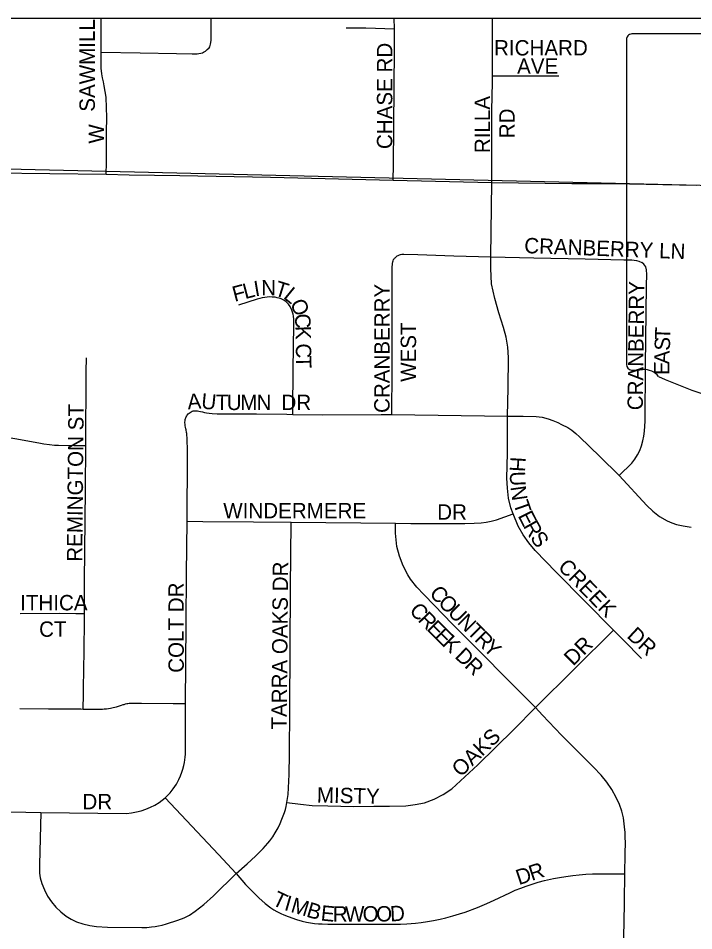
# Model space of a CAD drawing. Extents: x 0 to 68, y 0 to 52.9.
# Drawn here: x 57.097 to 58.195, y 51.458 to 52.941 of the extents above; entities that cross this region are included whole.
import ezdxf

# ---------------------------------------------------------------- set-up
doc = ezdxf.new("R2010")
doc.units = 0
for name, color, linetype in [('Default', 7, 'Continuous'), ('GM_X_State_Route', 7, 'Continuous'), ('GM_X_State_Shield', 7, 'Continuous')]:
    doc.layers.add(name, color=color, linetype=linetype)

msp = doc.modelspace()

# ---------------------------------------------------------------- linework, layer by layer
at = {"layer": 'Default'}
msp.add_line((49.5172, 52.9414), (67.9972, 52.9414), dxfattribs=at)
for points in [[(58.9659, 52.9414), (58.9639, 52.6515), (56.2737, 52.715), (56.2751, 52.9414)], [(57.2317, 52.8861), (57.2318, 52.9414)], [(57.4041, 52.8904), (57.4073, 52.8933), (57.4085, 52.8952), (57.4091, 52.8971), (57.4096, 52.8992), (57.41, 52.9021), (57.4104, 52.9058), (57.4107, 52.9093), (57.4104, 52.9414)], [(57.7083, 52.9241), (57.7082, 52.9414)], [(57.8676, 52.8476), (57.8676, 52.866), (57.8678, 52.9414)], [(57.6299, 52.9258), (57.6617, 52.9259), (57.7083, 52.9241)], [(57.7062, 52.6784), (57.7068, 52.7024), (57.7087, 52.8915), (57.7083, 52.9241)], [(57.2317, 52.8861), (57.2951, 52.885), (57.3543, 52.8839), (57.3799, 52.8834), (57.3844, 52.8834), (57.3878, 52.8836), (57.3908, 52.884), (57.3941, 52.8846), (57.3964, 52.8854), (57.3984, 52.8863), (57.4012, 52.888), (57.4041, 52.8904)], [(57.2403, 52.6877), (57.2404, 52.7066), (57.2407, 52.7561), (57.2409, 52.7806), (57.2405, 52.7959), (57.2398, 52.8129), (57.2387, 52.8222), (57.2368, 52.8318), (57.2355, 52.8381), (57.2342, 52.8445), (57.233, 52.8512), (57.2321, 52.8605), (57.2318, 52.8771), (57.2317, 52.8861)], [(57.8669, 52.6745), (57.8668, 52.7916), (57.8675, 52.8377), (57.8676, 52.8476)], [(57.8676, 52.8476), (57.8813, 52.8476), (57.9755, 52.8476)], [(57.8651, 52.5536), (57.8669, 52.6745)], [(57.7096, 52.5522), (57.7128, 52.555), (57.7144, 52.556), (57.7165, 52.557), (57.7181, 52.5574), (57.7203, 52.5577), (57.7237, 52.5579), (57.7465, 52.5574), (57.8049, 52.5554), (57.8651, 52.5536)], [(57.704, 52.2971), (57.7047, 52.369), (57.7049, 52.5336), (57.705, 52.5379), (57.7052, 52.5407), (57.7053, 52.543), (57.7057, 52.5454), (57.7062, 52.5473), (57.7071, 52.549), (57.7078, 52.5501), (57.7086, 52.5512), (57.7096, 52.5522)], [(57.8651, 52.5536), (57.935, 52.5522), (58.0185, 52.5505), (58.0812, 52.5487), (58.0939, 52.5487), (58.1019, 52.5476), (58.1054, 52.5466), (58.1102, 52.5441)], [(57.8919, 52.2943), (57.8932, 52.3408), (57.8938, 52.39), (57.8925, 52.4065), (57.8898, 52.4229), (57.8857, 52.4389), (57.8783, 52.4624), (57.8713, 52.4858), (57.8662, 52.5096), (57.8652, 52.5346), (57.8651, 52.5536)], [(58.0733, 52.1979), (58.0939, 52.2183), (58.0988, 52.2248), (58.1032, 52.2317), (58.107, 52.2389), (58.11, 52.2465), (58.1122, 52.2543), (58.1138, 52.2623), (58.1149, 52.2704), (58.1159, 52.2867), (58.1161, 52.3764), (58.1182, 52.507), (58.1185, 52.5248), (58.1179, 52.5322), (58.1167, 52.5375), (58.1139, 52.5416), (58.1102, 52.5441)], [(57.5434, 52.2975), (57.5434, 52.304), (57.5439, 52.3702), (57.5449, 52.4433), (57.5451, 52.446), (57.5451, 52.4498), (57.5449, 52.4524), (57.5445, 52.4569), (57.5439, 52.4606), (57.543, 52.4637), (57.542, 52.4668), (57.539, 52.4727), (57.5362, 52.4767), (57.5327, 52.4802), (57.5287, 52.4832), (57.5264, 52.4844), (57.5243, 52.4853), (57.5212, 52.4864), (57.518, 52.4871), (57.5145, 52.4878), (57.5098, 52.4881), (57.5054, 52.4883), (57.5016, 52.488), (57.4979, 52.4877), (57.4934, 52.4869), (57.4896, 52.4859), (57.4855, 52.4848), (57.455, 52.4748)], [(57.2071, 52.2468), (57.2073, 52.269), (57.2075, 52.3428), (57.2076, 52.3674), (57.208, 52.3893)], [(57.3715, 52.1237), (57.3715, 52.1324), (57.3723, 52.2218), (57.3722, 52.2433), (57.3719, 52.2531), (57.3716, 52.2595), (57.3713, 52.2635), (57.3709, 52.2665), (57.3707, 52.2682), (57.3699, 52.2722), (57.3696, 52.2739), (57.3691, 52.2766), (57.3686, 52.279), (57.3683, 52.2815), (57.3681, 52.2835), (57.3681, 52.285), (57.3683, 52.2869), (57.3686, 52.2891), (57.369, 52.2906), (57.3695, 52.292), (57.3701, 52.2934), (57.3709, 52.2949), (57.3716, 52.2961), (57.3733, 52.2982), (57.3763, 52.3006)], [(57.3763, 52.3006), (57.3781, 52.3017), (57.3799, 52.3025), (57.3816, 52.3031), (57.3829, 52.3034), (57.3845, 52.3034), (57.3867, 52.3035), (57.3885, 52.3032), (57.3907, 52.3029), (57.3933, 52.3023), (57.3964, 52.3014), (57.3996, 52.3006), (57.4033, 52.2998), (57.4073, 52.2993), (57.4121, 52.2989), (57.4202, 52.2983), (57.4844, 52.2984), (57.5337, 52.2977), (57.5434, 52.2975)], [(57.5434, 52.2975), (57.5912, 52.2969), (57.6871, 52.2972), (57.704, 52.2971)], [(57.704, 52.2971), (57.8919, 52.2943)], [(57.9011, 52.1359), (57.8977, 52.1458), (57.894, 52.1614), (57.8919, 52.1774), (57.8911, 52.1936), (57.8919, 52.2344), (57.8922, 52.2754), (57.8919, 52.2943)], [(57.8919, 52.2943), (57.9175, 52.2948), (57.9389, 52.294), (57.9486, 52.2928), (57.9581, 52.2902), (57.9658, 52.2876), (57.9738, 52.2843), (57.9801, 52.2811), (57.9902, 52.276), (57.9968, 52.2716), (58.0031, 52.2665), (58.009, 52.261), (58.0424, 52.2288), (58.0733, 52.1979)], [(57.0371, 52.2625), (57.0498, 52.2624), (57.0604, 52.2622), (57.0706, 52.2616), (57.079, 52.2605), (57.0919, 52.2585), (57.1304, 52.2511), (57.1388, 52.2496), (57.1482, 52.2484), (57.1559, 52.2475), (57.1628, 52.2472), (57.1874, 52.247), (57.2071, 52.2468)], [(57.2046, 51.9738), (57.2047, 51.9858), (57.2046, 52.0263), (57.2065, 52.1755), (57.2071, 52.2468)], [(58.0733, 52.1979), (58.1183, 52.1496), (58.1285, 52.1401), (58.1392, 52.1313), (58.1514, 52.1243), (58.1591, 52.1209), (58.1669, 52.1184), (58.1773, 52.1165), (58.1906, 52.1143)], [(57.7102, 52.1205), (57.7349, 52.1202), (57.7905, 52.1199), (57.8229, 52.1199), (57.8381, 52.1205), (57.8495, 52.1212), (57.8577, 52.122), (57.8656, 52.1237), (57.8744, 52.1262), (57.9011, 52.1359)], [(58.0643, 51.9465), (57.9711, 52.0408), (57.9373, 52.0762), (57.9269, 52.0886), (57.9176, 52.1018), (57.9097, 52.1158), (57.9011, 52.1359)], [(57.369, 51.8274), (57.3702, 51.958), (57.3707, 52.0382), (57.3715, 52.1237)], [(57.3715, 52.1237), (57.3972, 52.1235), (57.4797, 52.1228), (57.5404, 52.1225)], [(57.5338, 51.6667), (57.5357, 51.6795), (57.5376, 51.7122), (57.5379, 51.7449), (57.5384, 51.8187), (57.5398, 52.0153), (57.5404, 52.1225)], [(57.5404, 52.1225), (57.7102, 52.1205)], [(57.9377, 51.8209), (57.802, 51.9571), (57.7735, 51.987), (57.7561, 52.0047), (57.7449, 52.0168), (57.7348, 52.0298), (57.7304, 52.0368), (57.7228, 52.0514), (57.7166, 52.0668), (57.7125, 52.0827), (57.711, 52.0936), (57.7104, 52.1044), (57.7102, 52.1205)], [(57.1006, 51.974), (57.1642, 51.9744), (57.1907, 51.974), (57.2046, 51.9738)], [(57.2026, 51.8185), (57.2032, 51.8426), (57.2035, 51.8524), (57.2042, 51.9131), (57.2046, 51.9627), (57.2046, 51.9738)], [(57.9377, 51.8209), (58.0643, 51.9465)], [(58.11, 51.9008), (58.0804, 51.9302), (58.0643, 51.9465)], [(57.0996, 51.8191), (57.1462, 51.8189), (57.1988, 51.8186), (57.2026, 51.8185)], [(57.2026, 51.8185), (57.2281, 51.8182), (57.234, 51.8185), (57.237, 51.8186), (57.2404, 51.8189), (57.2438, 51.8192), (57.2473, 51.8198), (57.2517, 51.8209), (57.2566, 51.8221), (57.265, 51.8248), (57.2679, 51.8257), (57.2693, 51.8261), (57.2713, 51.8267), (57.2738, 51.8273), (57.2754, 51.8276), (57.2774, 51.8279), (57.2798, 51.828), (57.2975, 51.8278), (57.3487, 51.8276), (57.369, 51.8274)], [(57.3606, 51.7098), (57.3628, 51.7158), (57.3644, 51.7205), (57.3661, 51.7265), (57.3672, 51.7314), (57.3678, 51.736), (57.3684, 51.7404), (57.3687, 51.745), (57.3688, 51.7579), (57.3691, 51.8055), (57.369, 51.8274)], [(57.5338, 51.6667), (57.5557, 51.6636), (57.5749, 51.6617), (57.6003, 51.6611), (57.6424, 51.66), (57.6751, 51.6603), (57.7004, 51.6603), (57.7267, 51.6612), (57.7422, 51.663), (57.7572, 51.6662), (57.7728, 51.6721), (57.7876, 51.6797), (57.8015, 51.689), (57.8441, 51.7278), (57.9026, 51.7852), (57.9377, 51.8209)], [(58.0829, 51.5503), (58.0834, 51.5831), (58.0836, 51.6022), (58.0835, 51.6093), (58.0831, 51.6176), (58.0824, 51.627), (58.0804, 51.6414), (58.0778, 51.6524), (58.0742, 51.663), (58.0689, 51.6748), (58.0618, 51.6875), (58.0536, 51.6995), (58.0445, 51.7108), (58.0321, 51.7237), (58.0076, 51.7482), (57.9798, 51.7761), (57.9488, 51.8085), (57.9377, 51.8209)], [(57.3362, 51.6743), (57.3441, 51.6822), (57.3489, 51.6886), (57.3541, 51.6965), (57.358, 51.7041), (57.3606, 51.7098)], [(57.1339, 51.6505), (57.2733, 51.6489), (57.2813, 51.6498), (57.2892, 51.6512), (57.297, 51.6532), (57.3046, 51.6557), (57.3121, 51.6588), (57.3193, 51.6624), (57.3262, 51.6665), (57.3362, 51.6743)], [(57.3362, 51.6743), (57.4226, 51.5821), (57.4512, 51.5511)], [(56.749, 51.6388), (56.7665, 51.6388), (56.8173, 51.638), (56.8412, 51.6384), (56.8563, 51.6386), (56.8633, 51.6387), (56.8709, 51.6392), (56.88, 51.6406), (56.8954, 51.6438), (56.9087, 51.6483), (56.9205, 51.6518), (56.9298, 51.6537), (56.9362, 51.6543), (56.9859, 51.6537), (57.1339, 51.6505)], [(57.4512, 51.5511), (57.4694, 51.5668), (57.4829, 51.5793), (57.4892, 51.5857), (57.4953, 51.5919), (57.5029, 51.6003), (57.5058, 51.604), (57.5109, 51.6109), (57.5149, 51.617), (57.5194, 51.6251), (57.5227, 51.6324), (57.5257, 51.6393), (57.5288, 51.6476), (57.5297, 51.6504), (57.5314, 51.6554), (57.5326, 51.6601), (57.5338, 51.6667)], [(57.1339, 51.6505), (57.1316, 51.566), (57.1316, 51.5586), (57.1319, 51.5518), (57.1331, 51.5439), (57.1356, 51.5348), (57.1397, 51.5243), (57.1448, 51.5144), (57.1511, 51.5051), (57.1583, 51.4965), (57.1663, 51.4887), (57.1751, 51.4818), (57.1832, 51.4768), (57.1919, 51.4727), (57.2024, 51.4691), (57.2134, 51.4665), (57.2245, 51.4649), (57.2423, 51.4641), (57.2979, 51.4631), (57.3059, 51.4635), (57.3139, 51.4644), (57.3199, 51.4652), (57.3251, 51.4661), (57.3308, 51.4673), (57.3382, 51.4692), (57.3565, 51.475), (57.3669, 51.479), (57.3754, 51.4834), (57.3847, 51.4896), (57.3986, 51.5008), (57.4143, 51.515), (57.4512, 51.5511)], [(57.4512, 51.5511), (57.4663, 51.5334), (57.4879, 51.5113), (57.4985, 51.5025), (57.5074, 51.4953), (57.5125, 51.4921), (57.5176, 51.4892), (57.5241, 51.4862), (57.529, 51.484), (57.536, 51.4811), (57.5493, 51.4762), (57.5583, 51.4736), (57.5657, 51.472), (57.5719, 51.4708), (57.5785, 51.47), (57.5853, 51.4694), (57.5908, 51.4692), (57.6, 51.4689), (57.7181, 51.4688), (57.7287, 51.4693), (57.7426, 51.4705), (57.7518, 51.4716), (57.7619, 51.4729), (57.7717, 51.4745), (57.7827, 51.477), (57.7918, 51.4791), (57.8033, 51.4822), (57.8141, 51.4854), (57.8236, 51.4885), (57.8434, 51.4959), (57.8586, 51.5024), (57.8703, 51.5079), (57.8961, 51.5199), (57.9047, 51.5238), (57.9137, 51.5274), (57.9223, 51.5306), (57.9356, 51.5351), (57.9421, 51.537), (57.9524, 51.5398), (57.9668, 51.5429), (57.9767, 51.5446), (57.9868, 51.5463), (57.9985, 51.548), (58.0086, 51.5491), (58.0193, 51.5498), (58.0305, 51.5504), (58.0763, 51.5503), (58.0829, 51.5503)], [(58.0808, 51.4047), (58.0808, 51.4339), (58.0815, 51.47), (58.0823, 51.5061), (58.0829, 51.5503)]]:
    msp.add_lwpolyline(points, dxfattribs=at)
at = {"layer": 'GM_X_State_Route'}
msp.add_lwpolyline([(55.9568, 52.709), (56.1871, 52.7045), (56.21, 52.7037), (56.3547, 52.7019), (56.3701, 52.7017), (56.4681, 52.7008), (56.6268, 52.6981), (56.6687, 52.6974), (56.6885, 52.6963), (56.7552, 52.6949), (56.7784, 52.6944), (56.9523, 52.6919), (57.0421, 52.6907), (57.0567, 52.6904), (57.2403, 52.6877), (57.2777, 52.6871), (57.3595, 52.6858), (57.5068, 52.6832), (57.7062, 52.6784), (57.8669, 52.6745), (57.9965, 52.6726), (58.0634, 52.6726), (58.1989, 52.6703)], dxfattribs=at)
at = {"layer": 'GM_X_State_Shield'}
for p, q in [((58.3491, 52.9159), (58.0943, 52.9159)), ((58.0857, 52.9068), (58.0857, 52.3785))]:
    msp.add_line(p, q, dxfattribs=at)
for centre, major_axis, start_param, end_param in [((58.0957, 52.9079), (0.0101, 0), 1.712693, 3.28349), ((58.0958, 52.3773), (0.0102, 0), 3.00124, 4.508301), ((58.0973, 52.4314), (0.0776, 0), 4.665946, 4.897461), ((58.1132, 52.348), (0.028, 0), 0.519207, 1.627899), ((58.4665, 52.8227), (0.6663, 0), 4.195997, 4.488961)]:
    msp.add_ellipse(centre, major_axis=major_axis, ratio=0.8, start_param=start_param, end_param=end_param, dxfattribs=at)

# ---------------------------------------------------------------- texts
at = {"layer": 'Default'}
for s, rotation, p in [('SAWMILL', 90, (57.2217, 52.7895)), ('CHASE RD', 90, (57.705, 52.7288)), ('RICHARD', 0, (57.8703, 52.8809)), ('AVE', 0, (57.9077, 52.8511)), ('RILLA', 90, (57.8637, 52.7222)), ('RD', 90, (57.9037, 52.7464)), ('W', 90, (57.2364, 52.7376)), ('CRANBERRY LN', 357.8368, (57.919, 52.5597)), ('I', 9.5701, (57.4822, 52.4891)), ('N', 0.5683, (57.4921, 52.4908)), ('T', 342.6623, (57.512, 52.4913)), ('CRANBERRY', 89.3271, (58.112, 52.3041)), ('F', 14.6657, (57.4487, 52.4803)), ('L', 14.7212, (57.4658, 52.4847)), ('L', 320.824, (57.5266, 52.4873)), ('CRANBERRY', 90, (57.7006, 52.2998)), ('O', 293.4942, (57.5384, 52.4787)), ('C', 272.7945, (57.5466, 52.4608)), ('K', 271.0055, (57.5476, 52.4412)), ('WEST', 90, (57.7436, 52.3504)), ('T', 87.978, (58.1565, 52.4183)), ('C', 271.02, (57.5481, 52.4126)), ('S', 88.0053, (58.1559, 52.4007)), ('A', 88.2729, (58.1552, 52.3788)), ('T', 271.0247, (57.5484, 52.3928)), ('E', 89.235, (58.155, 52.3613)), ('A', 4.1557, (57.3729, 52.3055)), ('U', 354.1546, (57.3937, 52.3071)), ('T', 359.1911, (57.418, 52.3047)), ('U', 359.9703, (57.436, 52.3045)), ('M', 0.0001, (57.458, 52.3045)), ('N', 0, (57.4844, 52.3045)), ('DR', 0, (57.5249, 52.3045)), ('REMINGTON ST', 89.4383, (57.2012, 52.0578)), ('H', 266.6977, (57.897, 52.229)), ('U', 272.2249, (57.8957, 52.2045)), ('N', 278.2373, (57.8968, 52.1796)), ('T', 289.2046, (57.9012, 52.1528)), ('WINDERMERE', 0, (57.4303, 52.1285)), ('DR', 0, (57.7779, 52.1263)), ('E', 297.0781, (57.9085, 52.1327)), ('R', 299.1728, (57.917, 52.1161)), ('S', 304.797, (57.928, 52.0966)), ('TARRA OAKS DR', 89.4885, (57.5334, 51.785)), ('CREEK', 314.2752, (57.9727, 52.0479)), ('COLT DR', 90, (57.3662, 51.8774)), ('C', 311.4258, (57.7639, 52.0058)), ('ITHICA', 0, (57.1003, 51.9789)), ('O', 314.3622, (57.778, 51.9899)), ('C', 311.924, (57.7313, 51.9777)), ('U', 314.9992, (57.7936, 51.9739)), ('R', 314.4342, (57.7454, 51.9621)), ('N', 314.9992, (57.8091, 51.9584)), ('CT', 0, (57.1311, 51.9359)), ('E', 315.261, (57.7595, 51.9477)), ('E', 315.6506, (57.7721, 51.9352)), ('T', 315, (57.8247, 51.9428)), ('DR', 317.1199, (58.0847, 51.9358)), ('K', 315.668, (57.7847, 51.9229)), ('R', 315, (57.8371, 51.9304)), ('DR', 45, (57.999, 51.8873)), ('Y', 315, (57.8511, 51.9164)), ('D', 315.6955, (57.8052, 51.9029)), ('R', 315.687, (57.821, 51.8875)), ('OAKS', 44.172, (57.8163, 51.7068)), ('MISTY', 358.6647, (57.5822, 51.6665)), ('DR', 0, (57.2015, 51.6555)), ('R', 17.9972, (57.9314, 51.5389)), ('D', 18.2552, (57.9106, 51.532)), ('T', 334.7669, (57.5081, 51.501)), ('I', 344.0169, (57.5281, 51.492)), ('M', 343.3391, (57.5386, 51.4889)), ('B', 343.6179, (57.564, 51.4813)), ('E', 354.276, (57.588, 51.4748)), ('R', 0.0653, (57.6083, 51.4729)), ('W', 0.1951, (57.6281, 51.4729)), ('O', 0.1967, (57.6567, 51.473)), ('O', 0.1967, (57.6787, 51.4731)), ('D', 2.5289, (57.7018, 51.4732))]:
    msp.add_text(s, height=0.025, rotation=rotation, dxfattribs=at).set_placement(p)

doc.saveas('drawing.dxf')
